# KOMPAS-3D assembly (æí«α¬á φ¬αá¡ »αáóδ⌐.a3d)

Referenced files in D:\МОДЕЛЬ ТАНКА Т90\ДЕТАЛИ\КОРПУС\МЕТАЛЛ\КОРПУС ЛИТОЙ\: экран правый.m3d
Referenced files in D:\МОДЕЛЬ ТАНКА Т90\ДЕТАЛИ\ОБЩИЕ ДЕТАЛИ\: шарнир экрана большой.m3d, шарниры ящиков.m3d
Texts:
  Сборка экран правый
  stalker61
